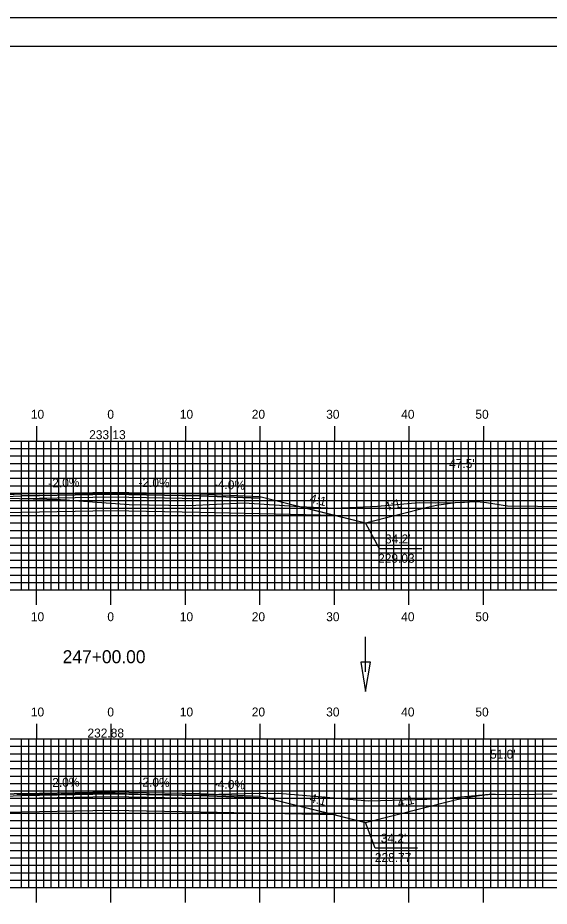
# Model space of a CAD drawing. Extents: x 1803110 to 1803453, y 442591 to 442811.
# Drawn here: x 1803263.1 to 1803334.5, y 442691.2 to 442810.5 of the extents above; entities that cross this region are included whole.
import ezdxf

# ---------------------------------------------------------------- set-up
doc = ezdxf.new("R2010")
doc.units = 0
for name, color, linetype in [('ANNOTATION', 7, 'Continuous'), ('BORDER', 7, 'Continuous'), ('D_Drainage_Ditch_Line', 7, 'Continuous'), ('D_Roadway_Centerline', 7, 'Continuous'), ('D_Roadway_Centerline_Text', 7, 'Continuous'), ('D_Roadway_Edge_Shoulder', 7, 'Continuous'), ('D_Roadway_Edge_TW', 7, 'Continuous'), ('D_Roadway_Pavement', 7, 'Continuous'), ('D_Roadway_SlopeLines', 7, 'Continuous'), ('D_Roadway_SubGrade', 7, 'Continuous'), ('D_Text_Standard', 7, 'Continuous'), ('H_V ANNOTATION', 7, 'Continuous'), ('MAJOR', 7, 'Continuous'), ('MINOR', 7, 'Continuous'), ('PLOT BOUNDARY', 7, 'Continuous'), ('S_Roadway_Centerline', 7, 'Continuous')]:
    doc.layers.add(name, color=color, linetype=linetype)

msp = doc.modelspace()

# ---------------------------------------------------------------- linework, layer by layer
at = {"layer": 'ANNOTATION'}
for points in [[(1803317.38, 442739.2), (1803311.68, 442739.2), (1803309.8, 442742.69)], [(1803316.8, 442698.98), (1803311.11, 442698.98), (1803309.8, 442702.44)]]:
    msp.add_lwpolyline(points, dxfattribs=at)
at = {"layer": 'BORDER'}
msp.add_lwpolyline([(1803126.03, 442596.67), (1803446.03, 442596.67), (1803446.03, 442806.67), (1803126.03, 442806.67)], close=True, dxfattribs=at)
at = {"layer": 'D_Drainage_Ditch_Line'}
msp.add_line((1803309.83, 442722.65), (1803309.83, 442727.35), dxfattribs=at)
msp.add_lwpolyline([(1803310.49, 442723.96), (1803309.17, 442723.96), (1803309.83, 442720.03)], close=True, dxfattribs=at)
at = {"layer": 'D_Roadway_Centerline'}
for points in [[(1803225.18, 442746.14), (1803226.43, 442746.1), (1803227.68, 442745.98), (1803228.93, 442745.78), (1803230.18, 442745.51), (1803241.45, 442742.69), (1803245.45, 442743.69), (1803255.63, 442746.24), (1803263.63, 442746.56), (1803275.63, 442746.8), (1803287.63, 442746.56), (1803295.63, 442746.24), (1803305.8, 442743.69), (1803309.8, 442742.69), (1803318.11, 442744.77), (1803319.36, 442745.05), (1803320.61, 442745.26), (1803321.86, 442745.4), (1803323.11, 442745.47)], [(1803222.65, 442706.55), (1803223.9, 442706.5), (1803225.15, 442706.37), (1803226.4, 442706.17), (1803227.65, 442705.89), (1803241.45, 442702.44), (1803245.45, 442703.44), (1803255.63, 442705.98), (1803263.63, 442706.3), (1803275.63, 442706.54), (1803287.63, 442706.3), (1803295.63, 442705.98), (1803305.8, 442703.44), (1803309.8, 442702.44), (1803321.68, 442705.41), (1803322.93, 442705.69), (1803324.18, 442705.93), (1803325.43, 442706.11), (1803326.68, 442706.24)]]:
    msp.add_lwpolyline(points, dxfattribs=at)
at = {"layer": 'D_Roadway_Edge_Shoulder'}
for points in [[(1803263.63, 442746.56), (1803255.63, 442746.24), (1803255.63, 442745.99), (1803263.63, 442746.31)], [(1803287.63, 442746.56), (1803295.63, 442746.24), (1803295.63, 442745.99), (1803287.63, 442746.31)], [(1803263.63, 442706.3), (1803255.63, 442705.98), (1803255.63, 442705.73), (1803263.63, 442706.05)], [(1803287.63, 442706.3), (1803295.63, 442705.98), (1803295.63, 442705.73), (1803287.63, 442706.05)]]:
    msp.add_lwpolyline(points, close=True, dxfattribs=at)
at = {"layer": 'D_Roadway_Edge_TW'}
for points in [[(1803263.63, 442746.31), (1803263.63, 442746.56), (1803275.63, 442746.8), (1803287.63, 442746.56), (1803287.63, 442746.31), (1803275.63, 442746.55)], [(1803263.63, 442706.05), (1803263.63, 442706.3), (1803275.63, 442706.54), (1803287.63, 442706.3), (1803287.63, 442706.05), (1803275.63, 442706.29)]]:
    msp.add_lwpolyline(points, close=True, dxfattribs=at)
at = {"layer": 'D_Roadway_Pavement'}
for points in [[(1803263.63, 442745.89), (1803263.63, 442746.31), (1803275.63, 442746.55), (1803287.63, 442746.31), (1803287.63, 442745.89), (1803275.63, 442746.13)], [(1803263.63, 442705.64), (1803263.63, 442706.05), (1803275.63, 442706.29), (1803287.63, 442706.05), (1803287.63, 442705.64), (1803275.63, 442705.88)]]:
    msp.add_lwpolyline(points, close=True, dxfattribs=at)
at = {"layer": 'D_Roadway_SlopeLines'}
for points in [[(1803295.63, 442746.24), (1803309.8, 442742.69)], [(1803309.8, 442742.69), (1803318.11, 442744.77), (1803319.36, 442745.05), (1803320.61, 442745.26), (1803321.86, 442745.4), (1803323.11, 442745.47)], [(1803309.8, 442702.44), (1803321.68, 442705.41), (1803322.93, 442705.69), (1803324.18, 442705.93), (1803325.43, 442706.11), (1803326.68, 442706.24)], [(1803295.63, 442705.98), (1803309.8, 442702.44)]]:
    msp.add_lwpolyline(points, dxfattribs=at)
at = {"layer": 'D_Roadway_SubGrade'}
for points in [[(1803263.63, 442744.06), (1803245.45, 442743.69), (1803255.63, 442746.24), (1803255.63, 442745.99), (1803263.63, 442746.31), (1803275.63, 442746.55), (1803287.63, 442746.31), (1803295.63, 442745.99), (1803295.63, 442746.24), (1803305.8, 442743.69), (1803287.63, 442744.06), (1803275.63, 442744.3)], [(1803263.63, 442703.8), (1803245.45, 442703.44), (1803255.63, 442705.98), (1803255.63, 442705.73), (1803263.63, 442706.05), (1803275.63, 442706.29), (1803287.63, 442706.05), (1803295.63, 442705.73), (1803295.63, 442705.98), (1803305.8, 442703.44), (1803287.63, 442703.8), (1803275.63, 442704.04)]]:
    msp.add_lwpolyline(points, close=True, dxfattribs=at)
at = {"layer": 'MAJOR'}
for p, q in [((1803265.63, 442755.67), (1803265.63, 442753.67)), ((1803275.63, 442755.67), (1803275.63, 442753.67)), ((1803285.63, 442755.67), (1803285.63, 442753.67)), ((1803295.63, 442755.67), (1803295.63, 442753.67)), ((1803305.63, 442755.67), (1803305.63, 442753.67)), ((1803315.63, 442755.67), (1803315.63, 442753.67)), ((1803325.63, 442755.67), (1803325.63, 442753.67)), ((1803135.63, 442753.67), (1803415.63, 442753.67)), ((1803135.63, 442753.67), (1803415.63, 442753.67)), ((1803265.63, 442733.67), (1803265.63, 442753.67)), ((1803275.63, 442733.67), (1803275.63, 442753.67)), ((1803285.63, 442733.67), (1803285.63, 442753.67)), ((1803295.63, 442733.67), (1803295.63, 442753.67)), ((1803305.63, 442733.67), (1803305.63, 442753.67)), ((1803315.63, 442733.67), (1803315.63, 442753.67)), ((1803325.63, 442733.67), (1803325.63, 442753.67)), ((1803135.63, 442748.67), (1803415.63, 442748.67)), ((1803135.63, 442743.67), (1803415.63, 442743.67)), ((1803135.63, 442738.67), (1803415.63, 442738.67)), ((1803135.63, 442733.67), (1803415.63, 442733.67)), ((1803135.63, 442733.67), (1803415.63, 442733.67)), ((1803265.63, 442731.66), (1803265.63, 442733.67)), ((1803275.63, 442731.66), (1803275.63, 442733.67)), ((1803285.63, 442731.66), (1803285.63, 442733.67)), ((1803295.63, 442731.66), (1803295.63, 442733.67)), ((1803305.63, 442731.66), (1803305.63, 442733.67)), ((1803315.63, 442731.66), (1803315.63, 442733.67)), ((1803325.63, 442731.66), (1803325.63, 442733.67)), ((1803265.63, 442715.67), (1803265.63, 442713.67)), ((1803275.63, 442715.67), (1803275.63, 442713.67)), ((1803285.63, 442715.67), (1803285.63, 442713.67)), ((1803295.63, 442715.67), (1803295.63, 442713.67)), ((1803305.63, 442715.67), (1803305.63, 442713.67)), ((1803315.63, 442715.67), (1803315.63, 442713.67)), ((1803325.63, 442715.67), (1803325.63, 442713.67)), ((1803135.63, 442713.67), (1803415.63, 442713.67)), ((1803135.63, 442713.67), (1803415.63, 442713.67)), ((1803265.63, 442693.67), (1803265.63, 442713.67)), ((1803275.63, 442693.67), (1803275.63, 442713.67)), ((1803285.63, 442693.67), (1803285.63, 442713.67)), ((1803295.63, 442693.67), (1803295.63, 442713.67)), ((1803305.63, 442693.67), (1803305.63, 442713.67)), ((1803315.63, 442693.67), (1803315.63, 442713.67)), ((1803325.63, 442693.67), (1803325.63, 442713.67)), ((1803135.63, 442708.67), (1803415.63, 442708.67)), ((1803135.63, 442703.67), (1803415.63, 442703.67)), ((1803135.63, 442698.67), (1803415.63, 442698.67)), ((1803135.63, 442693.67), (1803415.63, 442693.67)), ((1803135.63, 442693.67), (1803415.63, 442693.67)), ((1803265.63, 442691.66), (1803265.63, 442693.67)), ((1803275.63, 442691.66), (1803275.63, 442693.67)), ((1803285.63, 442691.66), (1803285.63, 442693.67)), ((1803295.63, 442691.66), (1803295.63, 442693.67)), ((1803305.63, 442691.66), (1803305.63, 442693.67)), ((1803315.63, 442691.66), (1803315.63, 442693.67)), ((1803325.63, 442691.66), (1803325.63, 442693.67))]:
    msp.add_line(p, q, dxfattribs=at)
at = {"layer": 'MINOR'}
for p, q in [((1803263.63, 442733.67), (1803263.63, 442753.67)), ((1803264.63, 442733.67), (1803264.63, 442753.67)), ((1803266.63, 442733.67), (1803266.63, 442753.67)), ((1803267.63, 442733.67), (1803267.63, 442753.67)), ((1803268.63, 442733.67), (1803268.63, 442753.67)), ((1803269.63, 442733.67), (1803269.63, 442753.67)), ((1803270.63, 442733.67), (1803270.63, 442753.67)), ((1803271.63, 442733.67), (1803271.63, 442753.67)), ((1803272.63, 442733.67), (1803272.63, 442753.67)), ((1803273.63, 442733.67), (1803273.63, 442753.67)), ((1803274.63, 442733.67), (1803274.63, 442753.67)), ((1803276.63, 442733.67), (1803276.63, 442753.67)), ((1803277.63, 442733.67), (1803277.63, 442753.67)), ((1803278.63, 442733.67), (1803278.63, 442753.67)), ((1803279.63, 442733.67), (1803279.63, 442753.67)), ((1803280.63, 442733.67), (1803280.63, 442753.67)), ((1803281.63, 442733.67), (1803281.63, 442753.67)), ((1803282.63, 442733.67), (1803282.63, 442753.67)), ((1803283.63, 442733.67), (1803283.63, 442753.67)), ((1803284.63, 442733.67), (1803284.63, 442753.67)), ((1803286.63, 442733.67), (1803286.63, 442753.67)), ((1803287.63, 442733.67), (1803287.63, 442753.67)), ((1803288.63, 442733.67), (1803288.63, 442753.67)), ((1803289.63, 442733.67), (1803289.63, 442753.67)), ((1803290.63, 442733.67), (1803290.63, 442753.67)), ((1803291.63, 442733.67), (1803291.63, 442753.67)), ((1803292.63, 442733.67), (1803292.63, 442753.67)), ((1803293.63, 442733.67), (1803293.63, 442753.67)), ((1803294.63, 442733.67), (1803294.63, 442753.67)), ((1803296.63, 442733.67), (1803296.63, 442753.67)), ((1803297.63, 442733.67), (1803297.63, 442753.67)), ((1803298.63, 442733.67), (1803298.63, 442753.67)), ((1803299.63, 442733.67), (1803299.63, 442753.67)), ((1803300.63, 442733.67), (1803300.63, 442753.67)), ((1803301.63, 442733.67), (1803301.63, 442753.67)), ((1803302.63, 442733.67), (1803302.63, 442753.67)), ((1803303.63, 442733.67), (1803303.63, 442753.67)), ((1803304.63, 442733.67), (1803304.63, 442753.67)), ((1803306.63, 442733.67), (1803306.63, 442753.67)), ((1803307.63, 442733.67), (1803307.63, 442753.67)), ((1803308.63, 442733.67), (1803308.63, 442753.67)), ((1803309.63, 442733.67), (1803309.63, 442753.67)), ((1803310.63, 442733.67), (1803310.63, 442753.67)), ((1803311.63, 442733.67), (1803311.63, 442753.67)), ((1803312.63, 442733.67), (1803312.63, 442753.67)), ((1803313.63, 442733.67), (1803313.63, 442753.67)), ((1803314.63, 442733.67), (1803314.63, 442753.67)), ((1803316.63, 442733.67), (1803316.63, 442753.67)), ((1803317.63, 442733.67), (1803317.63, 442753.67)), ((1803318.63, 442733.67), (1803318.63, 442753.67)), ((1803319.63, 442733.67), (1803319.63, 442753.67)), ((1803320.63, 442733.67), (1803320.63, 442753.67)), ((1803321.63, 442733.67), (1803321.63, 442753.67)), ((1803322.63, 442733.67), (1803322.63, 442753.67)), ((1803323.63, 442733.67), (1803323.63, 442753.67)), ((1803324.63, 442733.67), (1803324.63, 442753.67)), ((1803326.63, 442733.67), (1803326.63, 442753.67)), ((1803327.63, 442733.67), (1803327.63, 442753.67)), ((1803328.63, 442733.67), (1803328.63, 442753.67)), ((1803329.63, 442733.67), (1803329.63, 442753.67)), ((1803330.63, 442733.67), (1803330.63, 442753.67)), ((1803331.63, 442733.67), (1803331.63, 442753.67)), ((1803332.63, 442733.67), (1803332.63, 442753.67)), ((1803333.63, 442733.67), (1803333.63, 442753.67)), ((1803135.63, 442752.67), (1803415.63, 442752.67)), ((1803135.63, 442751.67), (1803415.63, 442751.67)), ((1803135.63, 442750.67), (1803415.63, 442750.67)), ((1803135.63, 442749.67), (1803415.63, 442749.67)), ((1803135.63, 442747.67), (1803415.63, 442747.67)), ((1803135.63, 442746.67), (1803415.63, 442746.67)), ((1803135.63, 442745.67), (1803415.63, 442745.67)), ((1803135.63, 442744.67), (1803415.63, 442744.67)), ((1803135.63, 442742.67), (1803415.63, 442742.67)), ((1803135.63, 442741.67), (1803415.63, 442741.67)), ((1803135.63, 442740.67), (1803415.63, 442740.67)), ((1803135.63, 442739.67), (1803415.63, 442739.67)), ((1803135.63, 442737.67), (1803415.63, 442737.67)), ((1803135.63, 442736.67), (1803415.63, 442736.67)), ((1803135.63, 442735.67), (1803415.63, 442735.67)), ((1803135.63, 442734.67), (1803415.63, 442734.67)), ((1803263.63, 442693.67), (1803263.63, 442713.67)), ((1803264.63, 442693.67), (1803264.63, 442713.67)), ((1803266.63, 442693.67), (1803266.63, 442713.67)), ((1803267.63, 442693.67), (1803267.63, 442713.67)), ((1803268.63, 442693.67), (1803268.63, 442713.67)), ((1803269.63, 442693.67), (1803269.63, 442713.67)), ((1803270.63, 442693.67), (1803270.63, 442713.67)), ((1803271.63, 442693.67), (1803271.63, 442713.67)), ((1803272.63, 442693.67), (1803272.63, 442713.67)), ((1803273.63, 442693.67), (1803273.63, 442713.67)), ((1803274.63, 442693.67), (1803274.63, 442713.67)), ((1803276.63, 442693.67), (1803276.63, 442713.67)), ((1803277.63, 442693.67), (1803277.63, 442713.67)), ((1803278.63, 442693.67), (1803278.63, 442713.67)), ((1803279.63, 442693.67), (1803279.63, 442713.67)), ((1803280.63, 442693.67), (1803280.63, 442713.67)), ((1803281.63, 442693.67), (1803281.63, 442713.67)), ((1803282.63, 442693.67), (1803282.63, 442713.67)), ((1803283.63, 442693.67), (1803283.63, 442713.67)), ((1803284.63, 442693.67), (1803284.63, 442713.67)), ((1803286.63, 442693.67), (1803286.63, 442713.67)), ((1803287.63, 442693.67), (1803287.63, 442713.67)), ((1803288.63, 442693.67), (1803288.63, 442713.67)), ((1803289.63, 442693.67), (1803289.63, 442713.67)), ((1803290.63, 442693.67), (1803290.63, 442713.67)), ((1803291.63, 442693.67), (1803291.63, 442713.67)), ((1803292.63, 442693.67), (1803292.63, 442713.67)), ((1803293.63, 442693.67), (1803293.63, 442713.67)), ((1803294.63, 442693.67), (1803294.63, 442713.67)), ((1803296.63, 442693.67), (1803296.63, 442713.67)), ((1803297.63, 442693.67), (1803297.63, 442713.67)), ((1803298.63, 442693.67), (1803298.63, 442713.67)), ((1803299.63, 442693.67), (1803299.63, 442713.67)), ((1803300.63, 442693.67), (1803300.63, 442713.67)), ((1803301.63, 442693.67), (1803301.63, 442713.67)), ((1803302.63, 442693.67), (1803302.63, 442713.67)), ((1803303.63, 442693.67), (1803303.63, 442713.67)), ((1803304.63, 442693.67), (1803304.63, 442713.67)), ((1803306.63, 442693.67), (1803306.63, 442713.67)), ((1803307.63, 442693.67), (1803307.63, 442713.67)), ((1803308.63, 442693.67), (1803308.63, 442713.67)), ((1803309.63, 442693.67), (1803309.63, 442713.67)), ((1803310.63, 442693.67), (1803310.63, 442713.67)), ((1803311.63, 442693.67), (1803311.63, 442713.67)), ((1803312.63, 442693.67), (1803312.63, 442713.67)), ((1803313.63, 442693.67), (1803313.63, 442713.67)), ((1803314.63, 442693.67), (1803314.63, 442713.67)), ((1803316.63, 442693.67), (1803316.63, 442713.67)), ((1803317.63, 442693.67), (1803317.63, 442713.67)), ((1803318.63, 442693.67), (1803318.63, 442713.67)), ((1803319.63, 442693.67), (1803319.63, 442713.67)), ((1803320.63, 442693.67), (1803320.63, 442713.67)), ((1803321.63, 442693.67), (1803321.63, 442713.67)), ((1803322.63, 442693.67), (1803322.63, 442713.67)), ((1803323.63, 442693.67), (1803323.63, 442713.67)), ((1803324.63, 442693.67), (1803324.63, 442713.67)), ((1803326.63, 442693.67), (1803326.63, 442713.67)), ((1803327.63, 442693.67), (1803327.63, 442713.67)), ((1803328.63, 442693.67), (1803328.63, 442713.67)), ((1803329.63, 442693.67), (1803329.63, 442713.67)), ((1803330.63, 442693.67), (1803330.63, 442713.67)), ((1803331.63, 442693.67), (1803331.63, 442713.67)), ((1803332.63, 442693.67), (1803332.63, 442713.67)), ((1803333.63, 442693.67), (1803333.63, 442713.67)), ((1803135.63, 442712.67), (1803415.63, 442712.67)), ((1803135.63, 442711.67), (1803415.63, 442711.67)), ((1803135.63, 442710.67), (1803415.63, 442710.67)), ((1803135.63, 442709.67), (1803415.63, 442709.67)), ((1803135.63, 442707.67), (1803415.63, 442707.67)), ((1803135.63, 442706.67), (1803415.63, 442706.67)), ((1803135.63, 442705.67), (1803415.63, 442705.67)), ((1803135.63, 442704.67), (1803415.63, 442704.67)), ((1803135.63, 442702.67), (1803415.63, 442702.67)), ((1803135.63, 442701.67), (1803415.63, 442701.67)), ((1803135.63, 442700.67), (1803415.63, 442700.67)), ((1803135.63, 442699.67), (1803415.63, 442699.67)), ((1803135.63, 442697.67), (1803415.63, 442697.67)), ((1803135.63, 442696.67), (1803415.63, 442696.67)), ((1803135.63, 442695.67), (1803415.63, 442695.67)), ((1803135.63, 442694.67), (1803415.63, 442694.67))]:
    msp.add_line(p, q, dxfattribs=at)
at = {"layer": 'PLOT BOUNDARY'}
msp.add_lwpolyline([(1803109.84, 442590.55), (1803449.84, 442590.55), (1803449.84, 442810.55), (1803109.84, 442810.55)], close=True, dxfattribs=at)
at = {"layer": 'S_Roadway_Centerline'}
for points in [[(1803259.64, 442746.04), (1803268.87, 442745.82), (1803278.07, 442745.13), (1803286.09, 442745), (1803293.53, 442745.37), (1803300.94, 442744.9), (1803305.7, 442744.66), (1803311.44, 442744.94), (1803316.47, 442745.36), (1803317.04, 442745.4), (1803319.25, 442745.38), (1803319.7, 442745.42), (1803320.87, 442745.39), (1803324.76, 442745.53), (1803326.05, 442745.43), (1803328.89, 442744.95), (1803336.93, 442744.86)], [(1803263.02, 442706.23), (1803267.02, 442706.24), (1803274.67, 442706.43), (1803280.81, 442706.23), (1803286.67, 442706.15), (1803293.51, 442706.32), (1803298.11, 442706.38), (1803301.36, 442706.09), (1803310.24, 442705.33), (1803319.59, 442705.62), (1803321.66, 442705.8), (1803326.4, 442706.24), (1803327.12, 442706.23), (1803327.25, 442706.24), (1803330.37, 442706.2), (1803334.86, 442706.27)]]:
    msp.add_lwpolyline(points, dxfattribs=at)

# ---------------------------------------------------------------- texts
at = {"layer": 'ANNOTATION'}
for s, rotation, p in [('-2.0%', 1.1458, (1803267.23, 442747.43)), ('-2.0%', 358.8542, (1803279.31, 442747.52)), ('-4.0%', 357.7094, (1803289.42, 442747.29)), ('4:1', 345.9638, (1803302.22, 442745.45)), ('4:1', 14.0362, (1803312.49, 442744.23)), ('-2.0%', 1.1458, (1803267.23, 442707.18)), ('-2.0%', 358.8542, (1803279.31, 442707.27)), ('-4.0%', 357.7094, (1803289.42, 442707.03)), ('4:1', 345.9638, (1803302.22, 442705.2)), ('4:1', 14.0362, (1803314.27, 442704.42))]:
    msp.add_text(s, height=1.2, rotation=rotation, dxfattribs=at).set_placement(p)
for s, p in [("34.2'", (1803312.42, 442739.92)), ('229.03', (1803311.5, 442737.32)), ("34.2'", (1803311.85, 442699.71)), ('228.77', (1803311.06, 442697.11))]:
    msp.add_text(s, height=1.2, dxfattribs=at).set_placement(p)
at = {"layer": 'D_Roadway_Centerline'}
for s, p in [('C', (1803275.62, 442746.8)), ('L', (1803275.63, 442746.79)), ('C', (1803275.62, 442706.54)), ('L', (1803275.63, 442706.54))]:
    msp.add_text(s, height=0.0146, dxfattribs=at).set_placement(p)
at = {"layer": 'D_Roadway_Centerline_Text'}
for s, p in [('233.13', (1803272.71, 442753.93)), ('232.88', (1803272.48, 442713.84))]:
    msp.add_text(s, height=1.2, dxfattribs=at).set_placement(p)
at = {"layer": 'D_Text_Standard'}
for s, p in [("47.5'", (1803321.03, 442750.05)), ("51.0'", (1803326.53, 442711))]:
    msp.add_text(s, height=1.2, dxfattribs=at).set_placement(p)
at = {"layer": 'H_V ANNOTATION'}
for s, height, p in [('10', 1.2, (1803264.88, 442756.67)), ('0', 1.2, (1803275.15, 442756.67)), ('10', 1.2, (1803284.88, 442756.67)), ('20', 1.2, (1803294.54, 442756.67)), ('30', 1.2, (1803304.53, 442756.67)), ('40', 1.2, (1803314.6, 442756.67)), ('50', 1.2, (1803324.56, 442756.67)), ('10', 1.2, (1803264.88, 442729.47)), ('0', 1.2, (1803275.15, 442729.47)), ('10', 1.2, (1803284.88, 442729.47)), ('20', 1.2, (1803294.54, 442729.47)), ('30', 1.2, (1803304.53, 442729.47)), ('40', 1.2, (1803314.6, 442729.47)), ('50', 1.2, (1803324.56, 442729.47)), ('247+00.00', 1.75, (1803269.15, 442723.82)), ('10', 1.2, (1803264.88, 442716.67)), ('0', 1.2, (1803275.15, 442716.67)), ('10', 1.2, (1803284.88, 442716.67)), ('20', 1.2, (1803294.54, 442716.67)), ('30', 1.2, (1803304.53, 442716.67)), ('40', 1.2, (1803314.6, 442716.67)), ('50', 1.2, (1803324.56, 442716.67))]:
    msp.add_text(s, height=height, dxfattribs=at).set_placement(p)

doc.saveas('drawing.dxf')
